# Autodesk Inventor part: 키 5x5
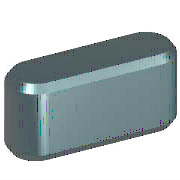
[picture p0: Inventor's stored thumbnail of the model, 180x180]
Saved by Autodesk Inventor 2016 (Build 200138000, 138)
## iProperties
IsCustomPart: 1
Created: 2012-02
Part Number: 키 5x5
Material: 강철, 연강
Description: 키 및 해당 키홈
Document SubType Name: Modeling
Standard: KS B 1311
Designer: mduedu
Standards Organization: KS
Language: ko-KR
Size Designation: 5 x 5 x 12
Categories: <MemberInstance><Categories><Category DisplayName="샤프트 부품" InternalName="7f7aeb1f-a693-4053-b835-cee3144e0d98" Mnemonic="SHFT"><Category DisplayName="키" Interna
Density: 1 g/cm^3
Appearance: 노란색
Author: mduedu
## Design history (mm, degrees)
workplane "Work Plane1"
workplane "Work Plane2"
sketch "스케치1"
  geometry: L1 (2.5, 2.5)-(9.5, 2.5); L2 (9.5, -2.5)-(2.5, -2.5); L3 (0, 9.4)-(0, -7.4) reference; L4 (-5, 0)-(30, 0) reference; L5 (12, 0)-(12, 7); A1 r 2.5 centre (2.5, 0) between (2.5, 2.5) and (2.5, -2.5); A2 r 2.5 centre (9.5, 0) between (9.5, -2.5) and (9.5, 2.5)
  constraints: 6 end point, 5 point on circle, 4 tangent, 3 point on line, 2 centre point, 1 horizontal, 1 parallel, 1 perpendicular
  dimensions: "d0" = 2.5 radius of A1 (= 0.5 x PB); "d13" = 2.5 radius of A2 (= 0.5 x PB); "d14" = 12 distance between parallel lines of L5 L3 (= NLG)
extrude "본체1" new body sketch "스케치1" taper "d3" = 0 deg; stored distance "d4" = 10
workplane "Work Plane3"
body "Solid1"
chamfer "모따기1" distance "d8" = 0.4 (= PHH); stored, may be unused: second distance "d9" = 0.4 (= PHH), angle "d15" = 45 deg
other parameters: "d1" = -3 (= -PNT), "d2" = 2 (= PH - PNT), "NLG" = 12 [user parameter; used in 3 equation terms], "PB" = 5 [user parameter; used in 2 equation terms], "PNT" = 3 [user parameter; used in 2 equation terms], "PH" = 5 [user parameter; used in 1 equation term], "PHH" = 0.4 [user parameter; used in 2 equation terms], "d10" = 0, "d16" = 0, "d17" = 0, "d18" = 0, "WDMIN" = 12 [user parameter], "PLB2" = 12 (= NLG) [user parameter], "WDMAX" = 17 [user parameter], "PLB1" = 12 (= NLG) [user parameter], "RR" = 0.16 [user parameter], "PUEB" = 2.3 [user parameter]
